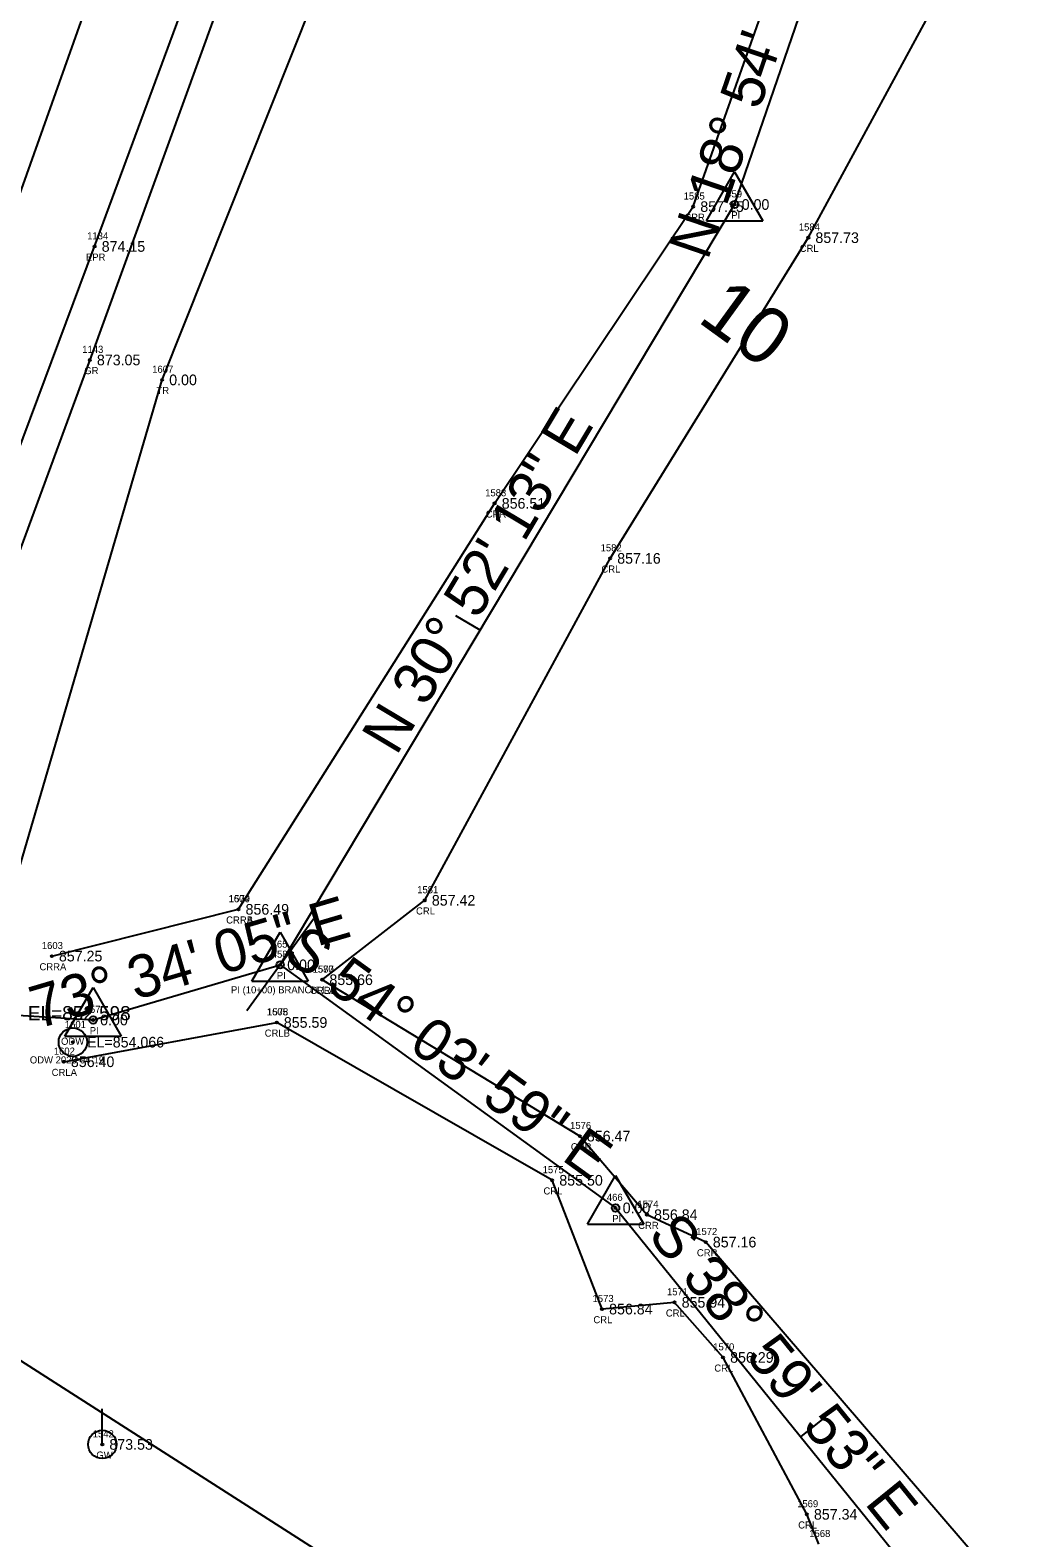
# Model space of a CAD drawing. Extents: x 1448136 to 1453623, y 1125056 to 1128842.
# Drawn here: x 1451276.4 to 1451414.6, y 1127430.4 to 1127643.1 of the extents above; entities that cross this region are included whole.
import ezdxf

# ---------------------------------------------------------------- set-up
doc = ezdxf.new("R2010")
doc.units = 0
for name, color, linetype in [('RD_EX_GuardRail', 7, 'Continuous'), ('RD_EX_GuardRail_txCode', 7, 'Continuous'), ('RD_EX_H2O', 7, 'Continuous'), ('RD_EX_H2O_txCode', 7, 'Continuous'), ('RD_EX_Road', 7, 'Continuous'), ('RD_EX_Road_txCode', 7, 'Continuous'), ('RD_EX_TX_GuardRail_ELEV', 7, 'Continuous'), ('RD_EX_TX_H2O_ELEV', 7, 'Continuous'), ('RD_EX_TX_Road_ELEV', 7, 'Continuous'), ('RD_EX_TX_UT_ELEV', 7, 'Continuous'), ('RD_EX_TX_VEG_ELEV', 7, 'Continuous'), ('RD_EX_UT', 7, 'Continuous'), ('RD_EX_UT_txCode', 7, 'Continuous'), ('RD_EX_VEG', 7, 'Continuous'), ('RD_EX_VEG_txCode', 7, 'Continuous'), ('RD_HC_Cl', 7, 'Continuous'), ('RD_HC_Data', 7, 'Continuous'), ('RD_HC_Data_Tic', 7, 'Continuous'), ('RD_HC_Survey_ELEV', 7, 'Continuous'), ('RD_HC_TX_Sta50', 7, 'Continuous'), ('RD_HC_txCode', 7, 'Continuous'), ('RD_SMD_Locator', 7, 'Continuous'), ('RD_TX_Pipe_ElevEX', 7, 'Continuous')]:
    doc.layers.add(name, color=color, linetype=linetype)

msp = doc.modelspace()

# ---------------------------------------------------------------- linework, layer by layer
at = {"layer": 'RD_EX_GuardRail'}
msp.add_lwpolyline([(1451325.19, 1127708.06), (1451304.64, 1127651.16), (1451284.82, 1127596.54), (1451254.55, 1127514.32), (1451234.22, 1127453.17)], dxfattribs=at)
at = {"layer": 'RD_EX_H2O'}
for p, q in [((1451279.46, 1127512.45), (1451305.79, 1127519.05)), ((1451281.15, 1127497.55), (1451311.19, 1127503.09))]:
    msp.add_line(p, q, dxfattribs=at)
for points in [[(1451305.79, 1127519.05), (1451341.93, 1127576.31), (1451369.94, 1127618.17), (1451384.18, 1127658.44), (1451431.45, 1127690.83), (1451437.15, 1127715.52), (1451468.26, 1127750.43), (1451480.2, 1127810.71), (1451541.05, 1127852.13)], [(1451317.62, 1127509.12), (1451332.07, 1127520.32), (1451358.22, 1127568.55), (1451386.18, 1127613.79), (1451406.69, 1127651.7), (1451450.85, 1127676.5), (1451462.31, 1127709.59), (1451484.41, 1127746.07), (1451494.56, 1127796.76), (1451552.88, 1127833.83)], [(1451410.48, 1127427.01), (1451371.71, 1127472.11), (1451363.42, 1127475.97), (1451353.94, 1127487.06), (1451317.62, 1127509.12)], [(1451387.68, 1127429.51), (1451385.97, 1127433.71), (1451374.15, 1127455.84), (1451367.31, 1127463.61), (1451357.08, 1127462.66), (1451350.05, 1127480.83), (1451311.19, 1127503.09)]]:
    msp.add_lwpolyline(points, dxfattribs=at)
for radius in [2, 0.15]:
    msp.add_circle((1451282.43, 1127500.31), radius, dxfattribs=at)
at = {"layer": 'RD_EX_Road'}
msp.add_lwpolyline([(1451218.61, 1127425.17), (1451235.09, 1127472.64), (1451251.12, 1127518.89), (1451267.38, 1127564.12), (1451285.5, 1127612.55), (1451301.55, 1127656.07), (1451320.37, 1127708.07)], dxfattribs=at)
at = {"layer": 'RD_EX_UT'}
msp.add_line((1451286.58, 1127443.57), (1451286.58, 1127448.57), dxfattribs=at)
msp.add_circle((1451286.58, 1127443.57), 2, dxfattribs=at)
at = {"layer": 'RD_EX_VEG'}
msp.add_lwpolyline([(1452001.9, 1127004.02), (1451950.15, 1126969.51), (1451866.38, 1127015.15), (1451796.48, 1127054.28), (1451721.5, 1127099.37), (1451558.29, 1127208.56), (1451484.08, 1127271.15), (1451430.37, 1127335.12), (1451374.3, 1127375.31), (1451350.11, 1127407.35), (1451262.13, 1127463.65), (1451257.69, 1127466.25), (1451295.02, 1127593.73), (1451319.4, 1127654.86), (1451348.07, 1127713.73)], dxfattribs=at)
at = {"layer": 'RD_HC_Cl'}
for p, q in [((1451174.85, 1127338.73), (1451307.37, 1127711.08)), ((1451375.78, 1127618.47), (1451388.51, 1127655.61)), ((1451311.67, 1127511.22), (1451375.78, 1127618.47)), ((1451119.35, 1127514.01), (1451285.28, 1127503.44)), ((1451285.28, 1127503.44), (1451311.67, 1127511.22)), ((1451311.67, 1127511.22), (1451358.99, 1127476.93)), ((1451358.99, 1127476.93), (1451404.11, 1127421.2))]:
    msp.add_line(p, q, dxfattribs=at)
at = {"layer": 'RD_HC_Data'}
for p, q in [((1451371.81, 1127616.18), (1451375.78, 1127623.06)), ((1451375.78, 1127623.06), (1451379.75, 1127616.18)), ((1451371.81, 1127616.18), (1451379.75, 1127616.18)), ((1451307.7, 1127508.93), (1451311.67, 1127515.81)), ((1451307.7, 1127508.93), (1451311.67, 1127515.81)), ((1451311.67, 1127515.81), (1451315.64, 1127508.93)), ((1451311.67, 1127515.81), (1451315.64, 1127508.93)), ((1451281.31, 1127501.15), (1451285.28, 1127508.03)), ((1451285.28, 1127508.03), (1451289.25, 1127501.15)), ((1451307.7, 1127508.93), (1451315.64, 1127508.93)), ((1451307.7, 1127508.93), (1451315.64, 1127508.93)), ((1451281.31, 1127501.15), (1451289.25, 1127501.15)), ((1451355.02, 1127474.63), (1451358.99, 1127481.51)), ((1451358.99, 1127481.51), (1451362.96, 1127474.63)), ((1451355.02, 1127474.63), (1451362.96, 1127474.63))]:
    msp.add_line(p, q, dxfattribs=at)
for centre in [(1451375.78, 1127618.47), (1451311.67, 1127511.22), (1451311.67, 1127511.22), (1451285.28, 1127503.44), (1451358.99, 1127476.93)]:
    msp.add_circle(centre, 0.529, dxfattribs=at)
at = {"layer": 'RD_HC_Data_Tic'}
for p, q in [((1451339.88, 1127558.42), (1451336.45, 1127560.47)), ((1451311.67, 1127511.22), (1451316.37, 1127517.7)), ((1451311.67, 1127511.22), (1451306.98, 1127504.75)), ((1451385.14, 1127444.63), (1451388.25, 1127447.15))]:
    msp.add_line(p, q, dxfattribs=at)
at = {"layer": 'RD_SMD_Locator'}
for centre in [(1451369.94, 1127618.17), (1451375.78, 1127618.47), (1451386.18, 1127613.79), (1451285.5, 1127612.55), (1451284.82, 1127596.54), (1451295.02, 1127593.73), (1451341.93, 1127576.31), (1451358.22, 1127568.55), (1451332.07, 1127520.32), (1451305.79, 1127519.05), (1451305.79, 1127519.05), (1451279.46, 1127512.45), (1451311.67, 1127511.22), (1451311.67, 1127511.22), (1451317.62, 1127509.12), (1451317.62, 1127509.12), (1451285.28, 1127503.44), (1451311.19, 1127503.09), (1451311.19, 1127503.09), (1451281.15, 1127497.55), (1451353.94, 1127487.06), (1451350.05, 1127480.83), (1451358.99, 1127476.93), (1451363.42, 1127475.97), (1451371.71, 1127472.11), (1451357.08, 1127462.66), (1451367.31, 1127463.61), (1451374.15, 1127455.84), (1451286.58, 1127443.57), (1451385.97, 1127433.71)]:
    msp.add_circle(centre, 0.15, dxfattribs=at)

# ---------------------------------------------------------------- texts
at = {"layer": 'RD_EX_GuardRail_txCode'}
for s, p in [('1143', (1451283.75, 1127597.54)), ('GR', (1451284.04, 1127594.54))]:
    msp.add_text(s, height=1, dxfattribs=at).set_placement(p)
at = {"layer": 'RD_EX_H2O'}
msp.add_text('ODW', height=1, dxfattribs=at).set_placement((1451280.76, 1127499.94))
at = {"layer": 'RD_EX_H2O_txCode'}
for s, p in [('1585', (1451368.59, 1127619.17)), ('CRR', (1451368.69, 1127616.17)), ('1584', (1451384.84, 1127614.79)), ('CRL', (1451384.96, 1127611.79)), ('1583', (1451340.59, 1127577.31)), ('CRR', (1451340.68, 1127574.31)), ('1582', (1451356.88, 1127569.55)), ('CRL', (1451356.99, 1127566.55)), ('1581', (1451331, 1127521.32)), ('1604', (1451304.38, 1127520.05)), ('1579', (1451304.44, 1127520.05)), ('CRRA', (1451304.05, 1127517.05)), ('CRRB', (1451304.06, 1127517.05)), ('CRL', (1451330.84, 1127518.32)), ('1603', (1451278.05, 1127513.45)), ('CRRA', (1451277.72, 1127510.45)), ('1580', (1451316.24, 1127510.12)), ('1577', (1451316.27, 1127510.12)), ('CRRB', (1451315.9, 1127507.12)), ('CRLA', (1451315.9, 1127507.12)), ('1601', (1451281.3, 1127502.31)), ('1605', (1451309.78, 1127504.09)), ('1578', (1451309.84, 1127504.09)), ('CRLB', (1451309.49, 1127501.09)), ('CRLB', (1451309.49, 1127501.09)), ('1602', (1451279.74, 1127498.55)), ('ODW 2023-04-19', (1451276.36, 1127497.31)), ('CRLA', (1451279.44, 1127495.55)), ('1576', (1451352.57, 1127488.06)), ('CRR', (1451352.68, 1127485.06)), ('1575', (1451348.7, 1127481.83)), ('CRL', (1451348.82, 1127478.83)), ('1574', (1451362.07, 1127476.97)), ('CRR', (1451362.17, 1127473.97)), ('1572', (1451370.36, 1127473.11)), ('CRR', (1451370.46, 1127470.11)), ('1571', (1451366.24, 1127464.61)), ('1573', (1451355.74, 1127463.66)), ('CRL', (1451366.08, 1127461.61)), ('CRL', (1451355.86, 1127460.66)), ('1570', (1451372.76, 1127456.84)), ('CRL', (1451372.92, 1127453.84)), ('1569', (1451384.6, 1127434.71)), ('CRL', (1451384.75, 1127431.71)), ('1568', (1451386.31, 1127430.51))]:
    msp.add_text(s, height=1, dxfattribs=at).set_placement(p)
at = {"layer": 'RD_EX_Road_txCode'}
for s, p in [('1134', (1451284.44, 1127613.55)), ('EPR', (1451284.27, 1127610.55))]:
    msp.add_text(s, height=1, dxfattribs=at).set_placement(p)
at = {"layer": 'RD_EX_TX_GuardRail_ELEV'}
msp.add_text('873.05', height=1.5, dxfattribs=at).set_placement((1451285.82, 1127595.79))
at = {"layer": 'RD_EX_TX_H2O_ELEV'}
for s, p in [('857.15', (1451370.94, 1127617.42)), ('857.73', (1451387.18, 1127613.04)), ('856.51', (1451342.93, 1127575.56)), ('857.16', (1451359.22, 1127567.8)), ('857.42', (1451333.07, 1127519.57)), ('856.49', (1451306.79, 1127518.3)), ('856.49', (1451306.79, 1127518.3)), ('857.25', (1451280.46, 1127511.7)), ('855.66', (1451318.62, 1127508.37)), ('855.66', (1451318.62, 1127508.37)), ('855.59', (1451312.19, 1127502.34)), ('855.59', (1451312.19, 1127502.34)), ('EL=854.066', (1451284.43, 1127499.56)), ('856.40', (1451282.15, 1127496.8)), ('856.47', (1451354.94, 1127486.31)), ('855.50', (1451351.05, 1127480.08)), ('856.84', (1451364.42, 1127475.22)), ('857.16', (1451372.71, 1127471.36)), ('856.84', (1451358.08, 1127461.91)), ('855.94', (1451368.31, 1127462.86)), ('856.29', (1451375.15, 1127455.09)), ('857.34', (1451386.97, 1127432.96))]:
    msp.add_text(s, height=1.5, dxfattribs=at).set_placement(p)
at = {"layer": 'RD_EX_TX_Road_ELEV'}
msp.add_text('874.15', height=1.5, dxfattribs=at).set_placement((1451286.5, 1127611.8))
at = {"layer": 'RD_EX_TX_UT_ELEV'}
msp.add_text('873.53', height=1.5, dxfattribs=at).set_placement((1451287.58, 1127442.82))
at = {"layer": 'RD_EX_TX_VEG_ELEV'}
msp.add_text('0.00', height=1.5, dxfattribs=at).set_placement((1451296.02, 1127592.98))
at = {"layer": 'RD_EX_UT_txCode'}
for s, p in [('1542', (1451285.23, 1127444.57)), ('GW', (1451285.74, 1127441.57))]:
    msp.add_text(s, height=1, dxfattribs=at).set_placement(p)
at = {"layer": 'RD_EX_VEG_txCode'}
for s, p in [('1607', (1451293.62, 1127594.73)), ('TR', (1451294.23, 1127591.73))]:
    msp.add_text(s, height=1, dxfattribs=at).set_placement(p)
at = {"layer": 'RD_HC_Data'}
for s, rotation, p in [('N 18%%d 54\' 53" E', 71.0852, (1451371.99, 1127610.48)), ('N 30%%d 52\' 13" E', 59.1297, (1451328.07, 1127540.6)), ('N 73%%d 34\' 05" E', 16.432, (1451269.76, 1127499.9)), ('S 54%%d 03\' 59" E', 324.0664, (1451311.84, 1127512.34)), ('S 38%%d 59\' 53" E', 308.998, (1451363.4, 1127473.06))]:
    msp.add_text(s, height=6, rotation=rotation, dxfattribs=at).set_placement(p)
at = {"layer": 'RD_HC_Survey_ELEV'}
for p in [(1451376.78, 1127617.72), (1451312.67, 1127510.47), (1451312.67, 1127510.47), (1451286.28, 1127502.69), (1451359.99, 1127476.18)]:
    msp.add_text('0.00', height=1.5, dxfattribs=at).set_placement(p)
at = {"layer": 'RD_HC_TX_Sta50'}
msp.add_text('10', height=8, rotation=324.0664, dxfattribs=at).set_placement((1451370.36, 1127602.07))
at = {"layer": 'RD_HC_txCode'}
for s, p in [('459', (1451374.6, 1127619.47)), ('PI', (1451375.31, 1127616.47)), ('465', (1451310.47, 1127513.64)), ('458', (1451310.49, 1127512.22)), ('PI', (1451311.2, 1127509.22)), ('PI (10+00) BRANCH 1', (1451304.74, 1127507.2)), ('457', (1451284.1, 1127504.44)), ('PI', (1451284.81, 1127501.44)), ('466', (1451357.76, 1127477.93)), ('PI', (1451358.52, 1127474.93))]:
    msp.add_text(s, height=1, dxfattribs=at).set_placement(p)
at = {"layer": 'RD_TX_Pipe_ElevEX'}
msp.add_text('EL=852.598', height=2, dxfattribs=at).set_placement((1451276.09, 1127503.4))

doc.saveas('drawing.dxf')
